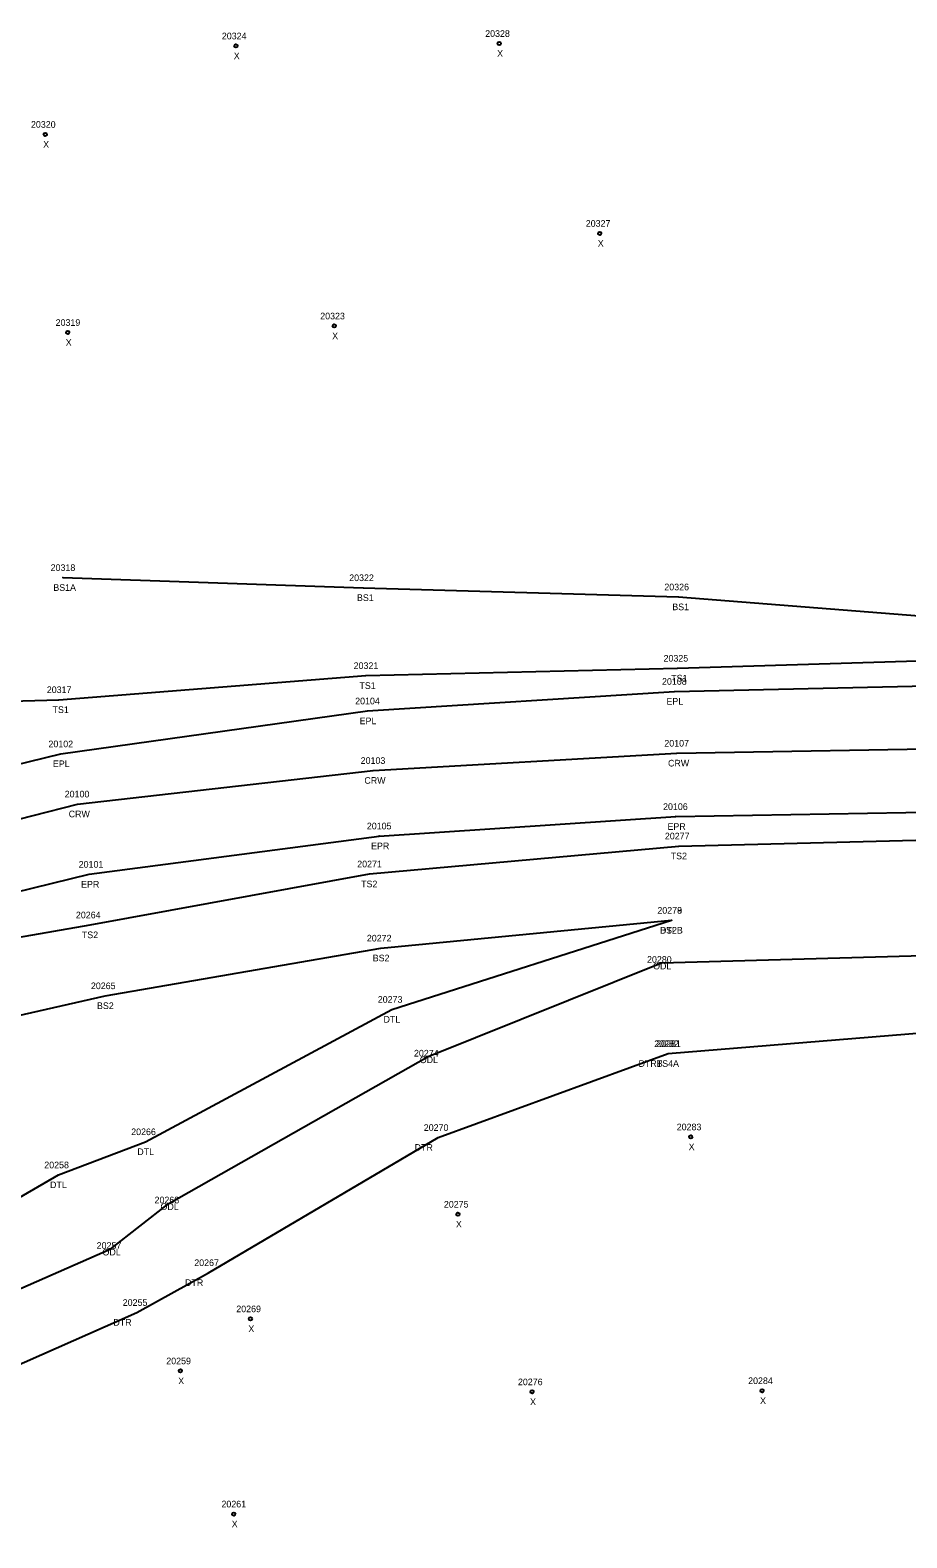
# Model space of a CAD drawing. Extents: x 1965722 to 1969964, y 1117078 to 1118461.
# Drawn here: x 1967961.8 to 1968094, y 1117810.7 to 1118038.1 of the extents above; entities that cross this region are included whole.
import ezdxf

# ---------------------------------------------------------------- set-up
doc = ezdxf.new("R2010")
doc.units = 0
for name, color, linetype in [('RD_DTM_BkLn1', 7, 'Continuous'), ('RD_DTM_BkLn2', 7, 'Continuous'), ('RD_EX_H2O', 7, 'Continuous'), ('RD_EX_H2O_txCode', 7, 'Continuous'), ('RD_EX_Road', 7, 'Continuous'), ('RD_EX_Road_txCode', 7, 'Continuous'), ('RD_SMD_Locator', 7, 'Continuous'), ('RD_SMD_Misc', 7, 'Continuous')]:
    doc.layers.add(name, color=color, linetype=linetype)

msp = doc.modelspace()

# ---------------------------------------------------------------- linework, layer by layer
at = {"layer": 'RD_DTM_BkLn1'}
msp.add_lwpolyline([(1967878.98, 1117895.46), (1967922.07, 1117909.4), (1967968.89, 1117921.38), (1968013.49, 1117926.44), (1968059.29, 1117929.05), (1968105.63, 1117929.86), (1968159.12, 1117928.97), (1968212.65, 1117927.25), (1968318.5, 1117923.95), (1968422.42, 1117919.39), (1968529.36, 1117916.3)], dxfattribs=at)
at = {"layer": 'RD_DTM_BkLn2'}
for points in [[(1967966.69, 1117955.54), (1968012.01, 1117954.01), (1968059.56, 1117952.62), (1968105.42, 1117949)], [(1967874.77, 1117908.42), (1967879.51, 1117916.91), (1967881.27, 1117924.39), (1967885.24, 1117929.22), (1967913.7, 1117935.63), (1967966.11, 1117937.12), (1968012.39, 1117940.75), (1968059.42, 1117941.87), (1968105.44, 1117943.27), (1968158.32, 1117942.95), (1968212.48, 1117942.1), (1968371.25, 1117933.41), (1968422.85, 1117933.68), (1968531.49, 1117931.42)], [(1967884.1, 1117882.92), (1967891.06, 1117879.24), (1967898.84, 1117879.11), (1967924.17, 1117888.04), (1967954.33, 1117900.3), (1967970.81, 1117903.15), (1968012.93, 1117910.83), (1968059.62, 1117915.05), (1968105.25, 1117916.2), (1968157.57, 1117912.09), (1968210.74, 1117910.77), (1968320.32, 1117907.54), (1968423.18, 1117904.83), (1968528.99, 1117899.6)], [(1967864, 1117905.28), (1967874.64, 1117878.97), (1967881.18, 1117873.82), (1967887.49, 1117871.9), (1967896.22, 1117872.02), (1967926.22, 1117878.93), (1967959.79, 1117889.45), (1967973.08, 1117892.46), (1968014.67, 1117899.65), (1968058.49, 1117903.84)], [(1968058.02, 1117883.74), (1968104.17, 1117887.52), (1968156.67, 1117888.05), (1968209.1, 1117889.3), (1968320.79, 1117888.13), (1968422.17, 1117888.28), (1968528.68, 1117880.51)]]:
    msp.add_lwpolyline(points, dxfattribs=at)
at = {"layer": 'RD_EX_H2O'}
for points in [[(1967872.82, 1117824.49), (1967892.16, 1117820.53), (1967923.08, 1117840.53), (1967966.02, 1117865.44), (1967979.17, 1117870.44), (1968016.32, 1117890.41), (1968058.49, 1117903.84)], [(1967868.28, 1117817.14), (1967892.54, 1117814.5), (1967928.24, 1117834.22), (1967973.92, 1117854.29), (1967982.67, 1117861.15), (1968021.78, 1117883.3), (1968056.97, 1117897.44), (1968105.42, 1117898.77), (1968155.9, 1117899.84), (1968209.66, 1117898.76), (1968320.81, 1117895.57), (1968371.06, 1117895.25)], [(1967873.55, 1117813.3), (1967887.27, 1117810.69), (1967931.74, 1117824.33), (1967977.85, 1117844.69), (1967988.67, 1117850.69), (1968023.3, 1117871.08), (1968058.02, 1117883.74)]]:
    msp.add_lwpolyline(points, dxfattribs=at)
at = {"layer": 'RD_EX_Road'}
for points in [[(1967878.98, 1117895.46), (1967875.66, 1117903.48), (1967919.49, 1117917.47), (1967966.4, 1117928.95), (1968012.66, 1117935.42), (1968058.94, 1117938.37), (1968105.99, 1117939.39), (1968158.7, 1117938.56), (1968212.05, 1117937.21), (1968318.79, 1117933.28), (1968422.76, 1117929.93), (1968530.54, 1117925.7)], [(1967878.98, 1117895.46), (1967883.11, 1117885.63), (1967924.99, 1117899.59), (1967970.68, 1117910.78), (1968014.42, 1117916.56), (1968059.13, 1117919.49), (1968105.39, 1117920.31), (1968159.16, 1117919.37), (1968212.5, 1117917.97), (1968317.55, 1117914.44), (1968421.52, 1117910.75), (1968527.82, 1117906.41)]]:
    msp.add_lwpolyline(points, dxfattribs=at)
at = {"layer": 'RD_SMD_Locator'}
for centre, radius in [((1967992.8, 1118035.73), 0.25), ((1968032.52, 1118036.1), 0.25), ((1967964.05, 1118022.39), 0.25), ((1968047.69, 1118007.46), 0.25), ((1967967.44, 1117992.51), 0.25), ((1968007.64, 1117993.49), 0.25), ((1967966.69, 1117955.54), 0.001), ((1968012.01, 1117954.01), 0.001), ((1968059.56, 1117952.62), 0.001), ((1968059.42, 1117941.87), 0.001), ((1968012.39, 1117940.75), 0.001), ((1968058.94, 1117938.37), 0.001), ((1967966.11, 1117937.12), 0.001), ((1968012.66, 1117935.42), 0.001), ((1967966.4, 1117928.95), 0.001), ((1968059.29, 1117929.05), 0.001), ((1968013.49, 1117926.44), 0.001), ((1967968.89, 1117921.38), 0.001), ((1968059.13, 1117919.49), 0.001), ((1968014.42, 1117916.56), 0.001), ((1968059.62, 1117915.05), 0.001), ((1967970.68, 1117910.78), 0.001), ((1968012.93, 1117910.83), 0.001), ((1967970.81, 1117903.15), 0.001), ((1968058.49, 1117903.84), 0.001), ((1968058.49, 1117903.84), 0.001), ((1968014.67, 1117899.65), 0.001), ((1968056.97, 1117897.44), 0.001), ((1967973.08, 1117892.46), 0.001), ((1968016.32, 1117890.41), 0.001), ((1968021.78, 1117883.3), 0.001), ((1968058.02, 1117883.74), 0.001), ((1968058.02, 1117883.74), 0.001), ((1968061.4, 1117871.17), 0.25), ((1967979.17, 1117870.44), 0.001), ((1968023.3, 1117871.08), 0.001), ((1967966.02, 1117865.44), 0.001), ((1967982.67, 1117861.15), 0.001), ((1968026.29, 1117859.51), 0.25), ((1967973.92, 1117854.29), 0.001), ((1967988.67, 1117850.69), 0.001), ((1967977.85, 1117844.69), 0.001), ((1967995, 1117843.73), 0.25), ((1967984.42, 1117835.88), 0.25), ((1968037.48, 1117832.72), 0.25), ((1968072.17, 1117832.89), 0.25), ((1967992.48, 1117814.29), 0.25)]:
    msp.add_circle(centre, radius, dxfattribs=at)

# ---------------------------------------------------------------- texts
at = {"layer": 'RD_EX_H2O_txCode'}
for s, p in [('20279', (1968056.37, 1117904.84)), ('DTLB', (1968056.77, 1117901.84)), ('20280', (1968054.81, 1117897.44)), ('ODL', (1968055.73, 1117896.44)), ('20273', (1968014.2, 1117891.41)), ('DTL', (1968015.07, 1117888.41)), ('20281', (1968056.18, 1117884.74)), ('20274', (1968019.66, 1117883.3)), ('ODL', (1968020.53, 1117882.3)), ('DTRB', (1968053.53, 1117881.74)), ('20266', (1967977.01, 1117871.44)), ('20270', (1968021.14, 1117872.08)), ('DTL', (1967977.93, 1117868.44)), ('DTR', (1968019.76, 1117869.08)), ('20258', (1967963.9, 1117866.44)), ('DTL', (1967964.77, 1117863.44)), ('20268', (1967980.53, 1117861.15)), ('ODL', (1967981.43, 1117860.15)), ('20257', (1967971.8, 1117854.29)), ('ODL', (1967972.68, 1117853.29)), ('20267', (1967986.52, 1117851.69)), ('DTR', (1967985.13, 1117848.69)), ('20255', (1967975.73, 1117845.69)), ('DTR', (1967974.32, 1117842.69))]:
    msp.add_text(s, height=1, dxfattribs=at).set_placement(p)
at = {"layer": 'RD_EX_Road_txCode'}
for s, p in [('20108', (1968057.07, 1117939.37)), ('20104', (1968010.79, 1117936.42)), ('EPL', (1968057.74, 1117936.37)), ('EPL', (1968011.46, 1117933.42)), ('20102', (1967964.53, 1117929.95)), ('EPL', (1967965.2, 1117926.95)), ('20106', (1968057.23, 1117920.49)), ('20105', (1968012.55, 1117917.56)), ('EPR', (1968057.9, 1117917.49)), ('EPR', (1968013.19, 1117914.56)), ('20101', (1967969.09, 1117911.78)), ('EPR', (1967969.45, 1117908.78))]:
    msp.add_text(s, height=1, dxfattribs=at).set_placement(p)
at = {"layer": 'RD_SMD_Misc'}
for s, p in [('20324', (1967990.68, 1118036.73)), ('20328', (1968030.4, 1118037.1)), ('X', (1968032.2, 1118034.1)), ('X', (1967992.48, 1118033.73)), ('20320', (1967961.89, 1118023.39)), ('X', (1967963.73, 1118020.39)), ('20327', (1968045.57, 1118008.46)), ('X', (1968047.38, 1118005.46)), ('20319', (1967965.61, 1117993.51)), ('20323', (1968005.52, 1117994.49)), ('X', (1968007.32, 1117991.49)), ('X', (1967967.13, 1117990.51)), ('20318', (1967964.86, 1117956.54)), ('20322', (1968009.89, 1117955.01)), ('BS1A', (1967965.26, 1117953.54)), ('20326', (1968057.42, 1117953.62)), ('BS1', (1968011.06, 1117952.01)), ('BS1', (1968058.62, 1117950.62)), ('20321', (1968010.56, 1117941.75)), ('20325', (1968057.3, 1117942.87)), ('TS1', (1968011.43, 1117938.75)), ('TS1', (1968058.46, 1117939.87)), ('20317', (1967964.28, 1117938.12)), ('TS1', (1967965.15, 1117935.12)), ('20107', (1968057.42, 1117930.05)), ('20103', (1968011.62, 1117927.44)), ('CRW', (1968057.98, 1117927.05)), ('CRW', (1968012.18, 1117924.44)), ('20100', (1967966.98, 1117922.38)), ('CRW', (1967967.58, 1117919.38)), ('20277', (1968057.5, 1117916.05)), ('20271', (1968011.1, 1117911.83)), ('TS2', (1968058.38, 1117913.05)), ('TS2', (1968011.69, 1117908.83)), ('20278', (1968056.37, 1117904.84)), ('20264', (1967968.67, 1117904.15)), ('TS2', (1967969.57, 1117901.15)), ('20272', (1968012.55, 1117900.65)), ('BS2B', (1968056.79, 1117901.84)), ('BS2', (1968013.44, 1117897.65)), ('20265', (1967970.93, 1117893.46)), ('BS2', (1967971.85, 1117890.46)), ('20282', (1968055.9, 1117884.74)), ('TS4A', (1968056.28, 1117881.74)), ('20283', (1968059.29, 1117872.17)), ('X', (1968061.09, 1117869.17)), ('20275', (1968024.17, 1117860.51)), ('X', (1968025.98, 1117857.51)), ('20269', (1967992.86, 1117844.73)), ('X', (1967994.68, 1117841.73)), ('20259', (1967982.3, 1117836.88)), ('20284', (1968070.06, 1117833.89)), ('X', (1967984.1, 1117833.88)), ('20276', (1968035.34, 1117833.72)), ('X', (1968037.17, 1117830.72)), ('X', (1968071.86, 1117830.89)), ('20261', (1967990.62, 1117815.29)), ('X', (1967992.17, 1117812.29))]:
    msp.add_text(s, height=1, dxfattribs=at).set_placement(p)

doc.saveas('drawing.dxf')
